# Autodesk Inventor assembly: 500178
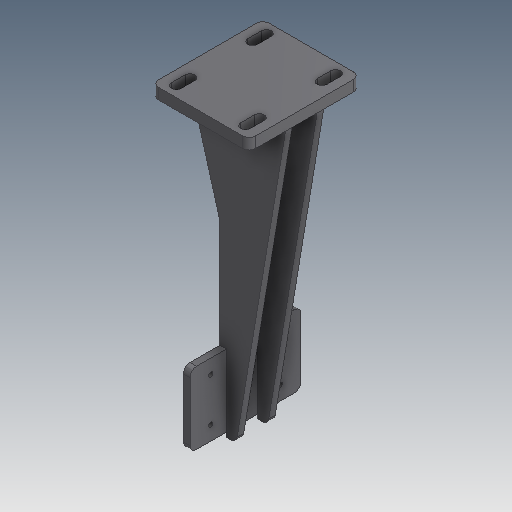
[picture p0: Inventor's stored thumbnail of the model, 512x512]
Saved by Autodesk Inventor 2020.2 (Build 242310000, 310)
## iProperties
Created: 1999-11
Part Number: 500178
Description: WMT-CP,FH,XX,MNT,FLIGHT_LUG
Document SubType Name: Assembly
Designer: sspink
Mass: 2019.01 g
Surface Area: 904.496 cm^2
Volume: 256.872 cm^3
Density: 7.86 g/cm^3
Control State: 0
Checked Out: False
Last Check In By: gpurviance
Last Check In Date: 1999-12-16
Master: False
Shininess: 0.0
Length Units: 11269
Angle Units: 11279
Time Units: 11290
Mass Units: 11283
Length Display Precision: 3
Angle Display Precision: 2
Compacted: True
Dimensions: 280x101,6x89 mm
Mass: 2,019 kg
DocNumber: 500178.iam
Folder: 01 - Themengebiete\Simplification\01 - Packaging machine\
VDS_Category: 3D Komponenten
Density: 0.0
Volumn: 0.0
Area: 0.0
PropertySet Name: Model Information
Author: sspink
Revision Number: -
Title: WMT-CP,FH,XX,MNT,FLIGHT_LUG
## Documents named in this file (4)
- D:\07 - DEMODATEN\OTX 2019 - Dataset - UPDATE - Dez2019\Designs\07-Packing machine\500178.iam
- D:\07 - DEMODATEN\OTX 2019 - Dataset - UPDATE - Dez2019\Designs\07-Packing machine\Parts\ADSK-011292.ipt
- D:\07 - DEMODATEN\OTX 2019 - Dataset - UPDATE - Dez2019\Designs\07-Packing machine\Parts\ADSK-011293.ipt
- D:\07 - DEMODATEN\OTX 2019 - Dataset - UPDATE - Dez2019\Designs\07-Packing machine\Parts\ADSK-011291.ipt
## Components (4 placed, 3 different names)
1. ADSK-011292:1 — Flush:1, Mate:1, Passend:2, Flush:2, Passend:3, Passend:4, Passend:7
2. ADSK-011293:1 — Flush:1, Passend:3, Passend:4, Passend:5, Passend:6
3. ADSK-011293:2 — Mate:1, Passend:2, Flush:2
4. ADSK-011291:1 — Passend:5, Passend:6, Passend:7
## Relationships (9: Mate 7, Flush 2)
- Flush:1: ADSK-011292:1 ↔ ADSK-011293:1
- Mate:1: ADSK-011292:1 ↔ ADSK-011293:2
- Passend:2 [Mate]: ADSK-011292:1 ↔ ADSK-011293:2
- Flush:2: ADSK-011292:1 ↔ ADSK-011293:2
- Passend:3 [Mate]: ADSK-011292:1 ↔ ADSK-011293:1
- Passend:4 [Mate]: ADSK-011292:1 ↔ ADSK-011293:1
- Passend:5 [Mate]: ADSK-011293:1 ↔ ADSK-011291:1
- Passend:6 [Mate]: ADSK-011293:1 ↔ ADSK-011291:1
- Passend:7 [Mate]: ADSK-011292:1 ↔ ADSK-011291:1
